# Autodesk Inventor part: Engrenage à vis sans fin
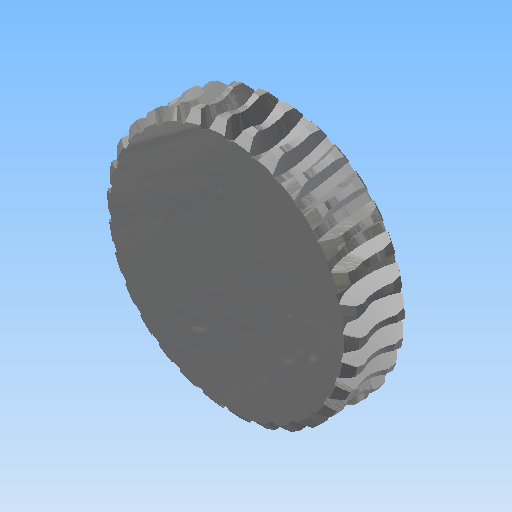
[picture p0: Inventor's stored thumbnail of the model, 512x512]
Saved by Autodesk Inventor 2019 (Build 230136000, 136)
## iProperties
Created: 2023-04
Part Number: Engrenage à vis sans fin
Material: Steel, Mild
Document SubType Name: Modeling
Designer: Thier
Categories: <?xml version="1.0" encoding="UTF-16"?> <MemberInstance><Categories><FamilyTemplate><FamilyTemplateParameter ValueType="xs:double" Id="1" ObjectReferenceKey="da
Density: 7.86 g/cm^3
Appearance: Steel
CustomPartVersion: 1
Author: Thier
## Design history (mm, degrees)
body "Solid1"
node "Plan de la dent"
sketch "Esquisse du corps de base"
  geometry: L1 (0, -14)-(0, 14) reference; L2 (0, 7.75)-(30.838, 7.75); L3 (30.838, 7.75)-(33, 5.921); L4 (-10, 0)-(60, 0) reference; L5 (33, 5.921)-(33, -5.921); L6 (0, -7.75)-(30.838, -7.75); L7 (0, 7.75)-(0, -7.75); L8 (30.838, -7.75)-(33, -5.921); C1 r 8 at (40, 0)
  constraints: 14 end point, 3 symmetric about line, 2 perpendicular, 2 point on line, 1 centre point, 1 collinear
  dimensions: "d50" = 40.2282 deg angle of L3 L2 (= da_fi); "d87" = 66 diameter of L5 L1 (= da_dae); "d89" = 16 diameter of C1 (= 2 x da_aw - da_da); "d92" = 15.5 distance of L2.start L6.start (= da_b); "d93" = 40 distance from line of C1.centre L7 (= da_aw)
revolve "Corps de base" stored, may be unused: angle "d35" = 90 deg
revolve "Corps de base 2" stored, may be unused: angle "d90" = 90 deg
workplane "Work Plane13"
revolve "Dent" stored, may be unused: angle "d43" = 90 deg
pattern_circular "Motif de la dent" dims angle "d46" = 360 deg
workplane "Work Plane14"
workplane "Work Plane15"
sketch "Esquisse de la dent"
  geometry: L1 (10, 5.301)-(10, -5.301) reference; L2 (-32.842, 0)-(-12.948, 0) reference; L3 (-30, 2.758)-(-30, -2.758); L4 (-30, -2.758)-(-22.4, -2.758); L5 (-22.4, -2.758)-(-17.6, -1.011); L6 (-17.6, -1.011)-(-17.6, 0); L7 (-17.6, 1.011)-(-22.4, 2.758); L8 (-22.4, 2.758)-(-30, 2.758); L9 (-17.6, 1.011)-(-17.6, 0); L10 (-20, 0)-(-20, -1.885)
  constraints: 16 end point, 4 perpendicular, 3 equal length, 2 point on line, 1 midpoint, 1 parallel, 1 vertical
  dimensions: "d38" = 40 distance between parallel lines of L1 L3 (= da_aw); "d39" = 20 deg angle of L7 L8 (= da_alfat); "d40" = 7.6 distance of L7.end L3.start (= 0.5 x da_df1); "d41" = 10 distance between parallel lines of L3 L10 (= 0.5 x da_d1); "d42" = 1.88496 distance of L10.start L10.end (= 0.3 x da_px)
sketch "Sketch8"
  geometry: C1 r 30.838 at (0, 0) reference; C2 r 30 at (0, 0)
  constraints: 1 centre point, 1 coincident
  dimensions: "d77" = 60 diameter of C2 (= da_dw)
body "Srf1"
feature "Diamètre primitif" dims "d78" = 15.5 (= da_b), "d79" = 0
other parameters: "da_aw" = 40 [user parameter; used in 5 equation terms], "da_fi" = 40.2282 deg [user parameter; used in 1 equation term], "da_b" = 15.5 [user parameter; used in 2 equation terms], "da_df" = 55.2 [user parameter], "da_da" = 64 [user parameter; used in 1 equation term], "da_beta" = 0.99669 [user parameter; used in 1 equation term], "da_alfat" = 20 deg [user parameter; used in 1 equation term], "da_df1" = 15.2 [user parameter; used in 1 equation term], "da_da1" = 24 [user parameter], "da_px" = 36 deg [user parameter; used in 1 equation term], "d37" = -0.99669 (computed from da_rightdir, da_beta), "d69" = 0, "d73" = 0, "d75" = 6 deg (computed from da_z), "da_dw" = 60 [user parameter; used in 1 equation term], "da_rightdir" = 0 [user parameter; used in 1 equation term], "d80" = 0, "d81" = 0, "d82" = 0, "d83" = 6 deg (computed from da_z), "d84" = 0, "d85" = 180 deg, "da_dae" = 66 [user parameter; used in 1 equation term]
